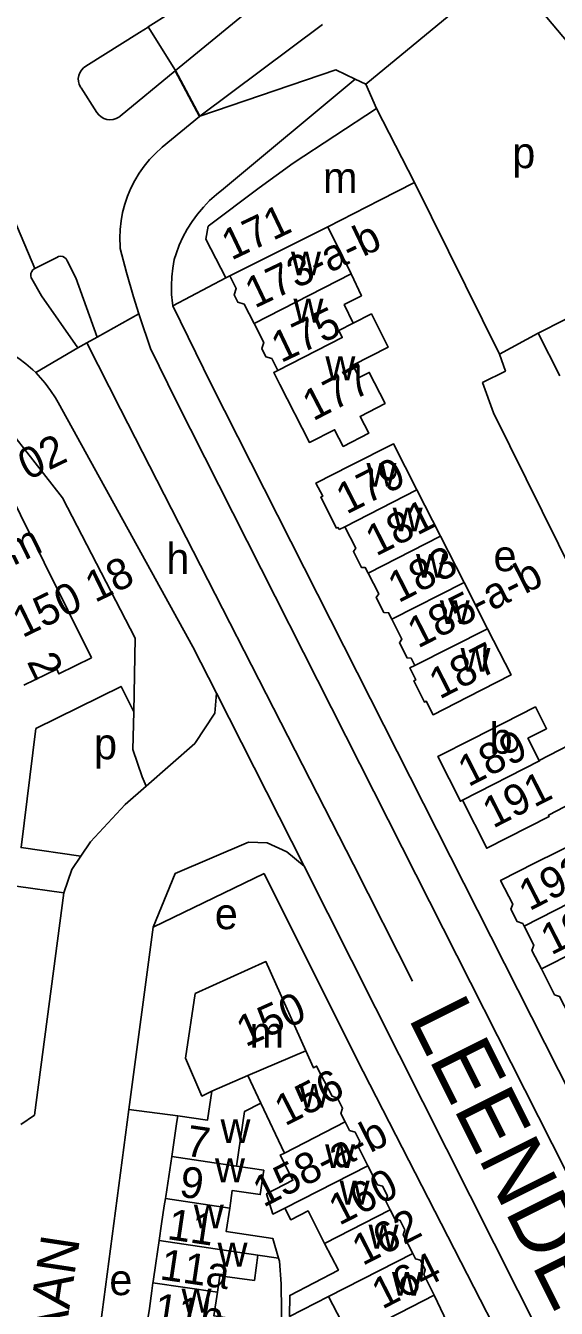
# Model space of a CAD drawing. Extents: x 161258 to 163262, y 380749 to 382054.
# Drawn here: x 162341.9 to 162410.3, y 381533.2 to 381698.7 of the extents above; entities that cross this region are included whole.
import ezdxf

# ---------------------------------------------------------------- set-up
doc = ezdxf.new("R2010")
doc.units = 0
for name, color, linetype in [('BLT_Basislijn', 7, 'Continuous'), ('BLT_Bebouwing', 7, 'Continuous'), ('BLT_Centroide', 7, 'Continuous'), ('BLT_Huisnummer', 7, 'Continuous'), ('BLT_Huisnummer_ tussenligend', 7, 'Continuous'), ('BLT_Huisnummer_reeks', 7, 'Continuous'), ('BLT_Onderverdeling_panden', 7, 'Continuous'), ('BLT_Straatnaam', 7, 'Continuous'), ('BLT_Straatnaam_hoofdweg', 7, 'Continuous'), ('BLT_Vlakafsluiter', 7, 'Continuous')]:
    doc.layers.add(name, color=color, linetype=linetype)

msp = doc.modelspace()

# ---------------------------------------------------------------- linework, layer by layer
at = {"layer": 'BLT_Basislijn'}
for p, q in [((162361.22, 381692.93), (162395.98, 381721.55)), ((162403.84, 381706.12), (162385.78, 381691.2)), ((162357.67, 381698.54), (162357.71, 381698.57)), ((162357.71, 381698.57), (162361.22, 381692.93)), ((162367.41, 381677.65), (162384.41, 381691.84)), ((162385.78, 381691.2), (162384.41, 381691.84)), ((162385.78, 381691.2), (162387.16, 381688.06)), ((162349.05, 381690.71), (162351.08, 381687.53)), ((162403, 381656.35), (162392.04, 381678.47)), ((162343.06, 381667.39), (162345.9, 381668.82)), ((162367.69, 381666.18), (162360.89, 381662.55)), ((162348.61, 381657.16), (162349.79, 381657.8)), ((162349.79, 381657.8), (162351.11, 381658.51)), ((162403, 381656.35), (162408, 381659.05)), ((162346.64, 381637.79), (162356, 381619.65)), ((162394.91, 381594.92), (162416.03, 381553.18)), ((162390.45, 381592.66), (162411.57, 381550.93)), ((162377.81, 381590.24), (162413.78, 381518.74)), ((162384.16, 381590.47), (162391.8, 381575.39)), ((162372.64, 381589.27), (162358.34, 381582.38)), ((162384.62, 381565.32), (162372.64, 381589.27)), ((162355.21, 381558.81), (162358.34, 381582.38)), ((162349.46, 381515.52), (162355.21, 381558.81)), ((162361.5, 381558), (162355.21, 381558.81)), ((162374.84, 381536.31), (162375.08, 381517.02)), ((162396.66, 381530.53), (162394.6, 381534.86))]:
    msp.add_line(p, q, dxfattribs=at)
for points in [[(162357.71, 381698.57), (162363.44, 381702.25), (162370.27, 381706.73), (162377.05, 381711.27), (162383.78, 381715.89), (162390.47, 381720.57), (162394.45, 381723.39)], [(162431.58, 381672.82), (162424.51, 381681.51), (162403.84, 381706.12)], [(162349.66, 381693.49), (162356.57, 381697.83), (162357.67, 381698.54)], [(162349.66, 381693.49), (162349.34, 381693.27), (162349.07, 381692.99), (162348.86, 381692.66), (162348.73, 381692.3), (162348.67, 381691.92), (162348.7, 381691.53), (162348.8, 381691.16), (162348.97, 381690.81), (162349.05, 381690.71)], [(162361.18, 381692.9), (162354.07, 381687.04), (162354.03, 381687.01), (162353.91, 381686.92), (162353.55, 381686.73), (162353.16, 381686.62), (162352.76, 381686.59), (162352.36, 381686.63), (162351.98, 381686.75), (162351.63, 381686.95), (162351.32, 381687.21), (162351.08, 381687.53)], [(162361.22, 381692.93), (162361.18, 381692.9)], [(162384.41, 381691.84), (162381.91, 381693.02), (162364.36, 381687.05)], [(162364.32, 381687.02), (162359.48, 381683.03), (162359.45, 381683), (162358.63, 381682.25), (162357.87, 381681.45), (162357.16, 381680.59), (162356.52, 381679.69), (162355.95, 381678.74), (162355.45, 381677.76), (162355.02, 381676.74), (162354.67, 381675.69), (162354.39, 381674.62), (162354.19, 381673.53), (162354.07, 381672.43), (162354.03, 381671.32), (162354.07, 381670.22), (162354.09, 381669.99)], [(162364.36, 381687.05), (162364.32, 381687.02)], [(162367.41, 381677.65), (162366.49, 381676.93), (162365.62, 381676.15), (162364.81, 381675.31), (162364.05, 381674.41), (162363.36, 381673.47), (162362.74, 381672.48), (162362.18, 381671.45), (162361.7, 381670.39), (162361.29, 381669.29), (162361.06, 381668.56)], [(162354.09, 381669.99), (162354.9, 381666.85), (162355.8, 381663.73), (162356.49, 381661.52)], [(162345.9, 381668.82), (162346.14, 381668.93), (162346.4, 381668.98), (162346.67, 381668.94), (162346.9, 381668.82), (162347.1, 381668.64), (162347.24, 381668.38)], [(162347.24, 381668.38), (162348.34, 381666.18), (162351.11, 381658.51)], [(162361.06, 381668.56), (162360.86, 381667.45), (162360.73, 381666.32), (162360.68, 381665.18), (162360.72, 381664.05), (162360.83, 381662.92), (162360.89, 381662.55)], [(162343.06, 381667.39), (162342.83, 381667.22), (162342.67, 381667), (162342.57, 381666.74), (162342.55, 381666.46), (162342.61, 381666.19), (162342.69, 381666.04)], [(162342.69, 381666.04), (162343.94, 381663.85), (162348.61, 381657.16)], [(162356.49, 381661.52), (162356.77, 381660.64), (162357.82, 381657.57), (162358, 381657.05)], [(162360.89, 381662.55), (162365.81, 381652.44), (162394.91, 381594.92)], [(162323.29, 381656.99), (162324.35, 381657.49), (162325.43, 381657.92), (162326.54, 381658.28), (162327.68, 381658.55), (162328.83, 381658.75), (162329.99, 381658.87), (162331.15, 381658.91), (162332.32, 381658.87), (162333.48, 381658.75), (162334.63, 381658.55), (162335.77, 381658.28), (162336.88, 381657.92), (162337.96, 381657.49), (162339.02, 381656.99), (162340.03, 381656.42), (162341.01, 381655.78), (162341.93, 381655.07), (162342.81, 381654.3), (162343.21, 381653.97)], [(162349.79, 381657.8), (162354.14, 381649.24), (162384.16, 381590.47)], [(162358, 381657.05), (162361.33, 381650.22), (162390.45, 381592.66)], [(162421.1, 381610.58), (162402.22, 381648.75), (162400.82, 381652.67), (162403.78, 381654.14), (162403, 381656.35)], [(162343.21, 381653.97), (162344.4, 381652.59), (162345.1, 381651.66), (162345.74, 381650.68), (162346.07, 381650.1)], [(162286.62, 381632.82), (162292.55, 381636.74), (162304.73, 381641.77), (162328.06, 381652.08), (162335.72, 381651.73), (162346.64, 381637.79)], [(162346.07, 381650.1), (162363.46, 381618.53), (162366.5, 381612.55)], [(162355.82, 381610.14), (162356, 381619.65)], [(162355.82, 381610.14), (162354.19, 381613.44), (162343.19, 381608.01)], [(162363.7, 381606.06), (162366.27, 381609.97), (162366.5, 381612.55)], [(162357.44, 381600.58), (162356.9, 381601.77), (162355.73, 381605.31), (162355.82, 381610.14)], [(162343.19, 381608.01), (162341.29, 381592.63), (162349.02, 381591.54)], [(162357.44, 381600.58), (162363.7, 381606.06)], [(162349.02, 381591.54), (162350.25, 381593.37), (162354.73, 381598.2), (162357.44, 381600.58)], [(162370.63, 381593.34), (162361.17, 381589.27), (162358.34, 381582.38)], [(162370.63, 381593.34), (162373.04, 381593.25), (162375.58, 381592.1), (162377.81, 381590.24)], [(162346.82, 381586.81), (162347.86, 381589.82), (162349.02, 381591.54)], [(162340.68, 381587.67), (162346.82, 381586.81)], [(162341.25, 381556.89), (162343.01, 381558.1), (162346.82, 381586.81)], [(162450.39, 381437.58), (162418.09, 381500), (162384.62, 381565.32)]]:
    msp.add_lwpolyline(points, dxfattribs=at)
at = {"layer": 'BLT_Bebouwing'}
for p, q in [((162387.16, 381688.06), (162376.39, 381680.99)), ((162392.04, 381678.47), (162387.16, 381688.06)), ((162372, 381677.82), (162365.42, 381672.83)), ((162380.87, 381672.78), (162383.86, 381666.68)), ((162367.69, 381666.18), (162368.21, 381666.45)), ((162410.79, 381653.53), (162408, 381659.05)), ((162337.06, 381643.91), (162350.39, 381617.14)), ((162392.36, 381638.8), (162395.4, 381632.83)), ((162383.06, 381634.06), (162382.32, 381633.69)), ((162395.4, 381632.83), (162398.44, 381626.86)), ((162398.44, 381626.86), (162401.47, 381620.89)), ((162372.22, 381559.64), (162375.26, 381553.21)), ((162369.09, 381551.51), (162372.62, 381550.98)), ((162371.84, 381540.02), (162371.41, 381536.77)), ((162371.84, 381540.02), (162374.51, 381539.63))]:
    msp.add_line(p, q, dxfattribs=at)
for points in [[(162376.39, 381680.99), (162372, 381677.82)], [(162392.04, 381678.47), (162387.58, 381676.2), (162380.87, 381672.78)], [(162365.42, 381672.83), (162365.14, 381671.19), (162367.69, 381666.18)], [(162368.21, 381666.45), (162369.05, 381664.8), (162368.78, 381663.97), (162369.26, 381663.04), (162370.08, 381662.77), (162371.35, 381660.28)], [(162383.86, 381666.68), (162385.2, 381663.86), (162382.98, 381662.73), (162384.13, 381660.32)], [(162415.85, 381663.03), (162411.39, 381660.77), (162408, 381659.05)], [(162384.13, 381660.32), (162386.48, 381661.52), (162388.65, 381657.25), (162384.08, 381654.93)], [(162371.35, 381660.28), (162372.59, 381657.84), (162372.33, 381657.05), (162372.87, 381656), (162373.64, 381655.75), (162374.41, 381654.24)], [(162374.69, 381652.4), (162378.49, 381644.93), (162381.74, 381646.58), (162382.86, 381644.42), (162386.15, 381646.12), (162385.02, 381648.3), (162388.24, 381649.97), (162386.2, 381653.98), (162384.9, 381653.32), (162384.08, 381654.93)], [(162374.41, 381654.24), (162373.89, 381653.97), (162374.69, 381652.4)], [(162382.32, 381633.69), (162382.18, 381633.97), (162381.99, 381633.87), (162379.96, 381637.86), (162380.2, 381637.98), (162379.33, 381639.68), (162383.79, 381641.95), (162389.32, 381644.77), (162392.36, 381638.8)], [(162386.05, 381628.07), (162385.69, 381628.79), (162385.2, 381628.81), (162384.16, 381630.85), (162384.46, 381631.3), (162383.06, 381634.06)], [(162389.12, 381622.12), (162388.7, 381622.95), (162388.1, 381622.98), (162387.12, 381624.9), (162387.43, 381625.37), (162386.05, 381628.07)], [(162392.07, 381616.15), (162391.6, 381617.08), (162391.09, 381617.11), (162390.1, 381619.05), (162390.43, 381619.55), (162389.12, 381622.12)], [(162401.47, 381620.89), (162404.51, 381614.92), (162398.9, 381612.06), (162394.45, 381609.79), (162393.56, 381611.53), (162393.33, 381611.42), (162391.95, 381614.14), (162392.21, 381614.28), (162391.43, 381615.82), (162392.07, 381616.15)], [(162350.39, 381617.14), (162346.18, 381615.06), (162345.89, 381615.67), (162341.67, 381613.59)], [(162408.14, 381603.87), (162406.67, 381606.76), (162409.08, 381607.98), (162407.64, 381610.79), (162399.5, 381606.65), (162395.04, 381604.38), (162397.97, 381598.62), (162398.22, 381598.75)], [(162408.14, 381603.87), (162421.1, 381610.58)], [(162425.35, 381602.17), (162414.51, 381596.66), (162413.36, 381598.92), (162409.31, 381596.82), (162409.4, 381596.64), (162401.37, 381592.56), (162398.22, 381598.75)], [(162419.02, 381589.05), (162416.08, 381594.85), (162407.61, 381590.66), (162403.15, 381588.39), (162404.71, 381585.34), (162404.49, 381584.67), (162405.3, 381583.08), (162406, 381582.85), (162406.17, 381582.51)], [(162406.17, 381582.51), (162407.42, 381580.05), (162407.2, 381579.36), (162408.42, 381576.97)], [(162378.02, 381566.42), (162372.87, 381577.93), (162363.76, 381573.78), (162362.49, 381565.45), (162364.62, 381560.55), (162365.89, 381561.2)], [(162408.42, 381576.97), (162410.12, 381573.63), (162410.76, 381573.42), (162412, 381570.99)], [(162383.1, 381557.22), (162382.54, 381558.32), (162382.77, 381559.02), (162382.11, 381560.3), (162381.42, 381560.53), (162379.42, 381564.44), (162379, 381564.22), (162378.02, 381566.42)], [(162365.89, 381561.2), (162365.34, 381557.43), (162361.5, 381558)], [(162369.09, 381551.51), (162370.13, 381558.57), (162372.22, 381559.64)], [(162361.5, 381558), (162361.39, 381557.26), (162360.75, 381552.78)], [(162386.04, 381551.57), (162384.79, 381554.03), (162385, 381554.68), (162384.38, 381555.89), (162383.66, 381556.12), (162383.1, 381557.22)], [(162360.75, 381552.78), (162359.95, 381547.61), (162359.91, 381547.33)], [(162375.26, 381553.21), (162374.72, 381552.94), (162376.37, 381549.7), (162372.96, 381547.96), (162373.78, 381545.32), (162375.31, 381546.11)], [(162368.21, 381546.11), (162368.54, 381548.38), (162372.15, 381547.85), (162372.62, 381550.98)], [(162388.91, 381545.87), (162388.33, 381547), (162388.55, 381547.69), (162387.93, 381548.91), (162387.29, 381549.12), (162386.04, 381551.57)], [(162359.91, 381547.33), (162359.77, 381546.4), (162359.42, 381544.07), (162359.1, 381541.9)], [(162374.51, 381539.63), (162373.76, 381542.18), (162367.76, 381543.06), (162368.21, 381546.11)], [(162380.44, 381541.54), (162378.32, 381545.74), (162376.08, 381544.6), (162375.31, 381546.11)], [(162391.81, 381540.25), (162390.6, 381542.63), (162390.81, 381543.3), (162390.2, 381544.5), (162389.49, 381544.73), (162388.91, 381545.87)], [(162359.1, 381541.9), (162358.67, 381538.98), (162358.33, 381536.64), (162358.3, 381536.45)], [(162380.97, 381534.69), (162375.94, 381532.12), (162375.95, 381534.83), (162382.23, 381538.09), (162380.44, 381541.54)], [(162394.6, 381534.86), (162393.24, 381537.53), (162393.43, 381538.13), (162392.8, 381539.36), (162392.17, 381539.56), (162391.81, 381540.25)], [(162374.84, 381536.31), (162374.63, 381539.23), (162374.51, 381539.63)], [(162366.62, 381535.23), (162366.94, 381537.36), (162371.41, 381536.77)], [(162358.3, 381536.45), (162358.15, 381535.43), (162357.84, 381533.15), (162357.52, 381531)], [(162370.16, 381529.14), (162370.51, 381531.54), (162366.17, 381532.18), (162366.62, 381535.23)], [(162380.97, 381534.69), (162383.73, 381529.3), (162390.15, 381532.58), (162394.6, 381534.86)]]:
    msp.add_lwpolyline(points, dxfattribs=at)
at = {"layer": 'BLT_Onderverdeling_panden'}
for p, q in [((162380.87, 381672.78), (162368.21, 381666.45)), ((162383.86, 381666.68), (162371.35, 381660.28)), ((162383.06, 381634.06), (162392.36, 381638.8)), ((162386.05, 381628.07), (162395.4, 381632.83)), ((162389.12, 381622.12), (162398.44, 381626.86)), ((162392.07, 381616.15), (162401.47, 381620.89)), ((162419.02, 381589.05), (162406.17, 381582.51)), ((162370.54, 381563.2), (162378.02, 381566.42)), ((162365.89, 381561.2), (162370.54, 381563.2)), ((162372.22, 381559.64), (162370.54, 381563.2)), ((162383.1, 381557.22), (162375.26, 381553.21)), ((162360.75, 381552.78), (162369.09, 381551.51)), ((162386.04, 381551.57), (162375.31, 381546.11)), ((162359.91, 381547.33), (162368.21, 381546.11)), ((162388.91, 381545.87), (162380.44, 381541.54)), ((162359.1, 381541.9), (162371.84, 381540.02)), ((162391.81, 381540.25), (162380.97, 381534.69)), ((162358.3, 381536.45), (162366.62, 381535.23))]:
    msp.add_line(p, q, dxfattribs=at)
for points in [[(162384.13, 381660.32), (162382.27, 381659.37), (162382.73, 381658.47), (162374.41, 381654.24)], [(162408.14, 381603.87), (162408.17, 381603.82), (162398.22, 381598.75)], [(162417.29, 381580.36), (162413.31, 381578.34), (162412.86, 381579.23), (162408.42, 381576.97)]]:
    msp.add_lwpolyline(points, dxfattribs=at)
at = {"layer": 'BLT_Vlakafsluiter'}
for p, q in [((162364.36, 381687.05), (162380.19, 381698.9)), ((162364.32, 381687.02), (162361.18, 381692.9)), ((162364.36, 381687.05), (162361.22, 381692.93)), ((162338.58, 381677.99), (162343.06, 381667.39)), ((162351.11, 381658.51), (162356.49, 381661.52)), ((162348.61, 381657.16), (162343.21, 381653.97))]:
    msp.add_line(p, q, dxfattribs=at)
msp.add_lwpolyline([(162366.5, 381612.55), (162377.81, 381590.24)], dxfattribs=at)

# ---------------------------------------------------------------- texts
at = {"layer": 'BLT_Centroide'}
for s, p in [('p', (162404.65, 381680.34)), ('m', (162380.24, 381677.12)), ('w', (162376.11, 381666.5)), ('w', (162376.43, 381660.41)), ('w', (162380.55, 381652.97)), ('w', (162385.85, 381639.22)), ('w', (162389.23, 381633.44)), ('h', (162360.03, 381627.96)), ('e', (162402.23, 381628.31)), ('w', (162392.24, 381627.47)), ('w', (162395.3, 381621.5)), ('w', (162397.98, 381615.34)), ('b', (162401.73, 381604.75)), ('p', (162350.7, 381604.04)), ('e', (162366.28, 381582.1)), ('m', (162370.75, 381566.8)), ('w', (162377.16, 381559.06)), ('w', (162367.02, 381554.5)), ('w', (162380.51, 381551.28)), ('w', (162366.31, 381549.44)), ('w', (162382.39, 381546.56)), ('w', (162363.58, 381543.47)), ('w', (162386.12, 381540.88)), ('w', (162366.64, 381538.56)), ('e', (162352.68, 381534.86)), ('w', (162389.14, 381534.78)), ('w', (162362, 381532.62))]:
    msp.add_text(s, height=4, dxfattribs=at).set_placement(p)
at = {"layer": 'BLT_Huisnummer'}
for s, rotation, p in [('171', 25.489, (162368.41, 381668.38)), ('177', 27.3918, (162378.96, 381647.63)), ('179', 26.9682, (162383.27, 381635.59)), ('183', 26.9642, (162389.96, 381624.16)), ('187', 26.9698, (162395.27, 381611.72)), ('189', 26.9668, (162398.99, 381600.42)), ('191', 26.9698, (162402.17, 381595.06)), ('150', 24.091, (162370.24, 381566.85)), ('156', 27.0506, (162375.34, 381556.62)), ('7', 351.6159, (162362.39, 381552.89)), ('160', 27.0631, (162382.33, 381543.79)), ('11', 351.609, (162360.02, 381542.11)), ('164', 27.0553, (162387.88, 381532.98)), ('11b', 351.6147, (162358.25, 381531.22))]:
    msp.add_text(s, height=4, rotation=rotation, dxfattribs=at).set_placement(p)
at = {"layer": 'BLT_Huisnummer_ tussenligend'}
for s, rotation, p in [('175', 25.489, (162374.82, 381655.15)), ('181', 26.9682, (162387.08, 381630.18)), ('9', 351.6159, (162361.58, 381547.61)), ('162', 27.0631, (162385.34, 381538.6)), ('11a', 351.6212, (162359.07, 381536.92))]:
    msp.add_text(s, height=4, rotation=rotation, dxfattribs=at).set_placement(p)
at = {"layer": 'BLT_Huisnummer_reeks'}
for s, rotation, p in [('173-a-b', 25.489, (162371.43, 381662.19)), ('150 02', 25.9009, (162332.81, 381635.44)), ('t/m', 25.9009, (162337.63, 381627.67)), ('150 18', 25.9009, (162341.47, 381619.65)), ('185-a-b', 26.9642, (162392.48, 381618.3)), ('2', 295.9009, (162341.99, 381616.64)), ('193-a-b', 26.9692, (162406.85, 381584.4)), ('195-a-b', 26.9692, (162409.67, 381578.68)), ('158-a-b', 27.0506, (162372.55, 381546.13))]:
    msp.add_text(s, height=4, rotation=rotation, dxfattribs=at).set_placement(p)
at = {"layer": 'BLT_Straatnaam'}
msp.add_text('ROOSTENLAAN', height=5, rotation=81.3532, dxfattribs=at).set_placement((162341.3, 381492.15))
at = {"layer": 'BLT_Straatnaam_hoofdweg'}
msp.add_text('LEENDERWEG', height=8, rotation=296.5347, dxfattribs=at).set_placement((162391.16, 381570.7))

doc.saveas('drawing.dxf')
